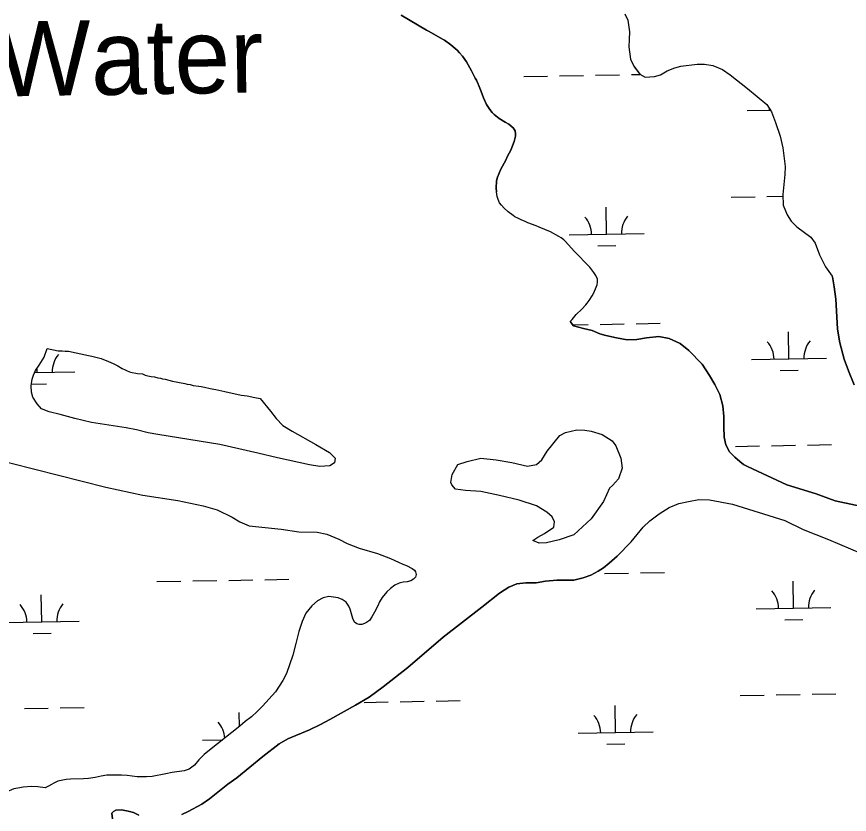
# Model space of a CAD drawing. Extents: x 3957609 to 3995875, y 234277 to 260273.
# Drawn here: x 3974548 to 3975660, y 243520 to 244584 of the extents above; entities that cross this region are included whole.
import ezdxf

# ---------------------------------------------------------------- set-up
doc = ezdxf.new("R2010")
doc.units = 0
for name, color, linetype in [('V-RIVR-IDEN', 7, 'Continuous'), ('V-TOPO-SHOR', 7, 'Continuous'), ('V-WETL-SWMP', 7, 'Continuous')]:
    doc.layers.add(name, color=color, linetype=linetype)

msp = doc.modelspace()

# ---------------------------------------------------------------- linework, layer by layer
at = {"layer": 'V-TOPO-SHOR'}
for points in [[(3975061.893, 244586.214), (3975095.656, 244566.531), (3975099.189, 244564.622), (3975116.687, 244554.464), (3975119.452, 244553.03), (3975128.031, 244546.87), (3975133.997, 244541.983), (3975136.284, 244539.784), (3975139.485, 244536.333), (3975143.44, 244531.631), (3975149.062, 244524.274), (3975155.544, 244512.263), (3975160.508, 244502.441), (3975162.171, 244499.784), (3975163.517, 244496.514), (3975166.07, 244491.216), (3975168.606, 244484.523), (3975171.578, 244475.966), (3975175.475, 244467.242), (3975177.289, 244464.274), (3975180.019, 244460.52), (3975183.366, 244456.449), (3975185.959, 244453.778), (3975192.535, 244448.267), (3975200.358, 244443.509), (3975205.275, 244440.962), (3975211.083, 244435.924), (3975213.965, 244431.858), (3975214.373, 244427.982), (3975214.327, 244424.887), (3975212.675, 244417.637), (3975208.022, 244406.25), (3975203.727, 244398.265), (3975201.327, 244392.883), (3975194.648, 244380.753), (3975190.317, 244370.136), (3975189.004, 244365.046), (3975188.707, 244355.298), (3975189.102, 244350.495)], [(3975360.305, 244588.291), (3975364.522, 244579.54), (3975366.469, 244563.991), (3975366.326, 244554.061), (3975365.562, 244544.296), (3975367.958, 244527.656), (3975372.935, 244517.649), (3975380.392, 244507.454), (3975387.629, 244503.624), (3975399.745, 244504.38), (3975407.851, 244506.901), (3975417.082, 244511.888), (3975426.92, 244516.246), (3975435.331, 244518.296), (3975456.942, 244520.93), (3975466.719, 244520.944), (3975477.864, 244519.075), (3975490.826, 244513.922), (3975500.966, 244506.791), (3975524.286, 244488.293), (3975549.743, 244467.283)], [(3975549.743, 244467.283), (3975556.276, 244457.567), (3975561.496, 244443.059), (3975567.747, 244424.656), (3975571.089, 244409.087), (3975574.458, 244384.519), (3975573.989, 244373.66), (3975571.12, 244347.01), (3975571.533, 244332.727), (3975577.241, 244319.761), (3975582.554, 244311.461), (3975589.89, 244303.75), (3975608.78, 244290.129), (3975614.558, 244281.82), (3975620.231, 244266.374), (3975628.222, 244250.272), (3975637.203, 244238.191)], [(3975287.191, 244177.265), (3975290.177, 244180.319), (3975295.531, 244186.586), (3975303.069, 244194.061), (3975308.257, 244199.558), (3975309.996, 244202.009), (3975312.83, 244205.372), (3975316.791, 244211.662), (3975319.017, 244215.809), (3975322.22, 244223.192), (3975323.193, 244226.272), (3975324.018, 244229.819), (3975323.771, 244234.003), (3975321.675, 244238.986), (3975318.947, 244242.896), (3975313.633, 244249.939), (3975292.893, 244271.289), (3975281.315, 244284.148), (3975279.026, 244286.348), (3975275.196, 244289.191), (3975272.282, 244290.936), (3975261.227, 244296.977), (3975253.69, 244300.338), (3975245.994, 244303.236), (3975241.842, 244305.153), (3975230.914, 244309.337), (3975226.298, 244311.26), (3975222.608, 244312.861), (3975217.688, 244315.256), (3975213.695, 244317.324), (3975211.085, 244318.911), (3975204.503, 244323.96), (3975199.156, 244328.68), (3975195.502, 244332.911), (3975193.225, 244335.885), (3975191.275, 244340.247), (3975190.098, 244344.446), (3975189.102, 244350.495)], [(3975666.755, 244093.119), (3975658.821, 244111.656), (3975653.007, 244127.065), (3975647.291, 244149.128), (3975644.463, 244167.433), (3975643.617, 244183.854), (3975642.097, 244207.094), (3975640.015, 244223.532), (3975637.733, 244237.032), (3975637.203, 244238.191)], [(3975287.191, 244177.265), (3975291.91, 244171.625), (3975305.015, 244168.029), (3975316.586, 244165.539), (3975327.049, 244161.207), (3975334.912, 244158.928), (3975349.414, 244155.62), (3975363.303, 244152.788), (3975376.158, 244153.373), (3975389.35, 244155.659), (3975405.936, 244157.277), (3975419.521, 244154.758), (3975434.127, 244147.889), (3975445.911, 244138.74), (3975463.604, 244120.528), (3975473.602, 244105.522), (3975480.703, 244093.5), (3975487.164, 244080.094), (3975491.125, 244065.023), (3975492.62, 244050.758), (3975492.419, 244036.986), (3975492.989, 244022.891), (3975495.01, 244012.801), (3975500.136, 244003.439), (3975507.001, 243996.374), (3975514.038, 243990.699), (3975518.929, 243986.447), (3975523.999, 243983.897), (3975576.735, 243959.295), (3975615.881, 243947.427), (3975640.975, 243937.93), (3975701.93, 243925.126)], [(3974873.241, 244074.663), (3974887.114, 244057.783), (3974894.712, 244048.075), (3974903.556, 244038.814), (3974916.139, 244031.202), (3974947.917, 244013.094), (3974966.028, 244002.46), (3974973.505, 243995.075), (3974972.643, 243988.896), (3974966.392, 243984.964), (3974952.915, 243984.075), (3974939.324, 243986.285), (3974896.582, 243995.575), (3974870.354, 244001.529), (3974819.6, 244013.409), (3974736.67, 244026.688), (3974724.012, 244029.039), (3974708.279, 244032.828), (3974694.541, 244035.505), (3974648.049, 244042.525), (3974626.15, 244048.106), (3974606.571, 244053.499), (3974591.758, 244056.655), (3974581.604, 244060.982), (3974575.814, 244067.413), (3974570.061, 244076.319), (3974568.304, 244083.156), (3974567.805, 244091.366), (3974568.863, 244100.328), (3974570.799, 244105.718), (3974573.678, 244112.178), (3974578.27, 244119.231), (3974584.928, 244129.971), (3974589.272, 244141.362)], [(3974589.272, 244141.362), (3974603.622, 244138.368), (3974608.883, 244138.292), (3974613.055, 244137.766), (3974617.542, 244137.7), (3974644.392, 244131.894), (3974648.866, 244131.054), (3974661.361, 244128.087), (3974664.437, 244126.805), (3974667.665, 244125.209), (3974677.207, 244121.357), (3974683.504, 244118.168), (3974689.181, 244114.681), (3974693.023, 244112.768), (3974695.948, 244111.641), (3974700.413, 244110.03), (3974709.672, 244108.039), (3974716.127, 244107.396)], [(3974716.127, 244107.396), (3974719.973, 244105.948), (3974723.522, 244105.123), (3974727.995, 244104.127), (3974732.32, 244103.445), (3974736.638, 244102.3), (3974740.191, 244101.784), (3974743.12, 244100.967), (3974746.824, 244100.295), (3974756.54, 244097.987), (3974772.742, 244094.502), (3974775.826, 244093.682), (3974779.842, 244093.16), (3974784.008, 244092.171), (3974791.573, 244090.977), (3974794.819, 244090.621), (3974799.141, 244089.783), (3974806.7, 244087.973), (3974814.417, 244086.465), (3974826.141, 244083.819), (3974848.209, 244079.32), (3974855.936, 244078.433), (3974866.423, 244075.959), (3974873.241, 244074.663)], [(3975339.935, 243955.119), (3975332.059, 243937.277), (3975315.396, 243914.12), (3975292.229, 243892.69), (3975272.542, 243885.901), (3975255.613, 243881.792), (3975245.811, 243881.391), (3975237.707, 243885.319), (3975244.3, 243889.577), (3975253.076, 243894.346), (3975265.714, 243902.868), (3975266.361, 243909.934), (3975263.193, 243916.51), (3975256.213, 243923.141), (3975242.186, 243931.507), (3975219.439, 243938.913), (3975192.869, 243945.282), (3975167.914, 243950.544), (3975147.798, 243951.924), (3975134.222, 243953.753), (3975129.403, 243959.266), (3975127.82, 243962.553), (3975129.61, 243973.41), (3975137.417, 243986.357), (3975149.992, 243990.529), (3975168.016, 243995.163), (3975188.66, 243992.687), (3975209.285, 243989.122), (3975230.439, 243984.463), (3975242.44, 243986.463), (3975249.608, 243992.89), (3975256.846, 244004.211), (3975273.478, 244025.193), (3975281.158, 244029.435), (3975296.444, 244033.023), (3975306.774, 244032.328), (3975315.464, 244031.114), (3975330.089, 244026.549), (3975343.573, 244018.189), (3975348.373, 244011.59), (3975355.209, 243995.165), (3975356.643, 243981.54), (3975352.086, 243967.458), (3975343.792, 243958.328), (3975339.935, 243955.119)], [(3974508.83, 243996.177), (3974667.366, 243956.417), (3974716.897, 243945.792), (3974763.53, 243938.305), (3974797.482, 243931.466), (3974815.826, 243926.246), (3974835.953, 243916.047), (3974846.392, 243910.169), (3974858.541, 243904.732), (3974901.508, 243900.392), (3974925.133, 243896.644), (3974949.429, 243896.29), (3974962.546, 243893.624), (3974978.547, 243887.045), (3974989.76, 243881.155), (3975005.454, 243874.737), (3975030.276, 243867.876), (3975047.51, 243860.97), (3975058.253, 243856.172)], [(3975350.001, 243864.308), (3975368.695, 243883.232), (3975384.77, 243902.964), (3975393.716, 243911.349), (3975406.08, 243920.61), (3975419.668, 243929.083), (3975432.286, 243934.473), (3975445.33, 243937.377), (3975459.141, 243939.81), (3975473.379, 243939.601), (3975504.251, 243933.58), (3975574.057, 243911.98), (3975598.493, 243899.862), (3975632.351, 243886.367), (3975676.508, 243867.925)], [(3975350.001, 243864.308), (3975339.581, 243854.847), (3975332.067, 243848.791), (3975324.547, 243843.97), (3975315.021, 243838.981), (3975304.72, 243835.221), (3975292.412, 243832.218), (3975269.456, 243831.925), (3975254.515, 243830.756), (3975241.894, 243828.677), (3975228.332, 243828.749), (3975216.015, 243827.289), (3975205.255, 243822.908), (3975193.129, 243814.976), (3975169.36, 243796.19), (3975117.981, 243756.125), (3975070.613, 243715.468), (3975037.64, 243689.536), (3975018.768, 243676.171), (3975000.653, 243665.12), (3974966.407, 243645.961), (3974953.965, 243639.26), (3974939.523, 243632.547), (3974910.318, 243620.506), (3974898.802, 243613.811), (3974876.872, 243596.575), (3974842.218, 243568.168), (3974830.405, 243559.621), (3974805.715, 243540.364), (3974795.587, 243533.216), (3974777.157, 243523.243), (3974769.012, 243519.497)], [(3975058.253, 243856.172), (3975063.967, 243853.587), (3975068.754, 243851.769), (3975076.556, 243847.812), (3975079.422, 243845.362), (3975080.898, 243843.062), (3975081.613, 243839.524), (3975080.71, 243836.13), (3975078.26, 243833.496), (3975074.732, 243831.088), (3975069.657, 243829.978), (3975064.5, 243829.255), (3975059.038, 243828.143), (3975053.432, 243825.491), (3975047.528, 243821.065), (3975042.625, 243816.568), (3975036.356, 243808.982), (3975032.619, 243803.028), (3975030.339, 243797.855), (3975026.077, 243789.28), (3975022.493, 243783.251), (3975019.212, 243778.378), (3975015.608, 243775.816), (3975012.614, 243774.102), (3975009.231, 243773.158), (3975005.767, 243772.906), (3975002.525, 243773.965), (3974999.584, 243776.181), (3974997.399, 243781.096), (3974993.705, 243793.552), (3974991.909, 243797.624), (3974988.488, 243802.608), (3974982.998, 243806.426), (3974977.671, 243808.627), (3974971.273, 243809.668), (3974965.26, 243810.401), (3974957.414, 243808.582), (3974949.968, 243804.609), (3974942.23, 243797.861), (3974934.511, 243787.957), (3974929.338, 243777.144), (3974925.107, 243763.795), (3974920.968, 243747.749), (3974917.288, 243732.169), (3974908.809, 243707.702), (3974903.705, 243698.199), (3974893.863, 243683.122), (3974876.647, 243664.069), (3974869.526, 243657.018), (3974861.715, 243649.809), (3974853.357, 243643.52), (3974846.388, 243637.316), (3974805.991, 243605.341), (3974798.788, 243599.213), (3974791.743, 243592.316), (3974785.933, 243585.348), (3974778.726, 243579.759), (3974772.039, 243577.642), (3974755.956, 243575.309), (3974747.572, 243573.796), (3974729.341, 243569.913), (3974721.564, 243569.556), (3974714.556, 243569.515), (3974709.086, 243569.714), (3974696.059, 243571.483), (3974688.432, 243571.977), (3974668.562, 243571.702), (3974661.253, 243570.502), (3974653.329, 243568.913), (3974644.406, 243567.398), (3974637.475, 243566.894), (3974620.227, 243566.326), (3974614.223, 243565.905), (3974603.298, 243563.683), (3974597.922, 243561.34), (3974594.621, 243559.472), (3974590.941, 243556.986), (3974586.239, 243554.745)], [(3974586.239, 243554.745), (3974576.648, 243556.388), (3974568.302, 243556.646), (3974556.872, 243555.65), (3974552.395, 243555.005), (3974544.679, 243553.414), (3974541.285, 243552.466), (3974537.279, 243550.588), (3974529.724, 243547.606), (3974522.175, 243544.005), (3974518.171, 243541.509), (3974515.556, 243539.485), (3974500.925, 243531.361), (3974496.612, 243529.172)], [(3974711.546, 243518.223), (3974704.437, 243521.881), (3974697.336, 243523.841), (3974688.082, 243525.326), (3974680.842, 243524.973), (3974677.461, 243523.413), (3974675.318, 243520.933), (3974676.289, 243513.39)]]:
    msp.add_lwpolyline(points, dxfattribs=at)
at = {"layer": 'V-WETL-SWMP'}
for p, q in [((3975369.267, 244507.158), (3975380.564, 244507.363)), ((3975225.291, 244504.54), (3975257.285, 244505.122)), ((3975273.283, 244505.413), (3975305.277, 244505.994)), ((3975321.275, 244506.285), (3975353.269, 244506.867)), ((3975523.48, 244459.212), (3975554.787, 244459.781)), ((3975502.174, 244343.373), (3975534.169, 244343.955)), ((3975550.166, 244344.246), (3975571.188, 244344.628)), ((3975335.982, 244293.914), (3975335.328, 244329.908)), ((3975285.99, 244293.005), (3975385.974, 244294.823)), ((3975324.265, 244278.267), (3975348.261, 244278.703)), ((3975327.323, 244173.665), (3975359.317, 244174.247)), ((3975375.315, 244174.538), (3975407.31, 244175.12)), ((3975290.759, 244173), (3975311.325, 244173.374)), ((3975579.52, 244127.501), (3975578.865, 244163.495)), ((3975529.528, 244126.592), (3975629.511, 244128.41)), ((3974572.345, 244109.187), (3974625.861, 244110.16)), ((3974575.87, 244109.251), (3974575.758, 244115.373)), ((3975567.802, 244111.854), (3975591.798, 244112.29)), ((3974568.077, 244093.676), (3974588.148, 244094.041)), ((3975508.222, 244010.753), (3975540.217, 244011.335)), ((3975556.215, 244011.626), (3975588.209, 244012.208)), ((3975604.207, 244012.498), (3975636.201, 244013.08)), ((3975333.371, 243841.045), (3975365.366, 243841.627)), ((3975381.363, 243841.918), (3975413.358, 243842.5)), ((3974735.562, 243830.175), (3974767.556, 243830.757)), ((3974783.554, 243831.048), (3974815.548, 243831.63)), ((3974831.546, 243831.921), (3974863.541, 243832.502)), ((3974879.538, 243832.793), (3974911.533, 243833.375)), ((3975585.568, 243794.881), (3975584.913, 243830.875)), ((3974581.918, 243776.631), (3974581.263, 243812.625)), ((3975535.576, 243793.972), (3975635.56, 243795.79)), ((3974531.926, 243775.722), (3974631.909, 243777.54)), ((3975573.85, 243779.234), (3975597.846, 243779.67)), ((3974570.2, 243760.985), (3974594.196, 243761.421)), ((3975514.27, 243678.133), (3975546.265, 243678.715)), ((3975562.263, 243679.006), (3975594.257, 243679.588)), ((3975610.255, 243679.878), (3975642.249, 243680.46)), ((3975012.445, 243669.008), (3975044.44, 243669.59)), ((3975060.438, 243669.881), (3975092.432, 243670.463)), ((3975108.43, 243670.754), (3975140.424, 243671.335)), ((3975348.078, 243628.674), (3975347.424, 243664.668)), ((3974558.612, 243660.756), (3974590.607, 243661.338)), ((3974606.605, 243661.629), (3974638.599, 243662.211)), ((3974845.937, 243636.959), (3974845.599, 243655.543)), ((3975298.086, 243627.765), (3975398.07, 243629.583)), ((3974796.261, 243618.64), (3974823.416, 243619.134)), ((3975336.361, 243613.027), (3975360.357, 243613.463))]:
    msp.add_line(p, q, dxfattribs=at)
for points in [[(3975492.989, 244022.891), (3975492.42, 244036.986), (3975492.62, 244050.759), (3975491.124, 244065.022), (3975487.164, 244080.094), (3975480.703, 244093.5), (3975473.602, 244105.522), (3975463.604, 244120.527), (3975445.912, 244138.74), (3975434.126, 244147.889), (3975419.521, 244154.757), (3975405.936, 244157.276), (3975389.35, 244155.659), (3975376.159, 244153.374), (3975363.303, 244152.787), (3975349.413, 244155.62), (3975334.911, 244158.927), (3975327.05, 244161.208), (3975316.587, 244165.539), (3975305.014, 244168.029), (3975291.909, 244171.625), (3975287.192, 244177.266), (3975290.178, 244180.318), (3975295.531, 244186.586), (3975303.069, 244194.061), (3975308.257, 244199.558), (3975309.995, 244202.009), (3975312.83, 244205.373), (3975316.791, 244211.661), (3975319.018, 244215.808), (3975322.22, 244223.191), (3975323.194, 244226.272), (3975324.019, 244229.82), (3975323.771, 244234.003), (3975321.676, 244238.986), (3975318.947, 244242.895), (3975313.632, 244249.938), (3975292.892, 244271.289), (3975281.315, 244284.149), (3975279.026, 244286.349), (3975275.197, 244289.191), (3975272.282, 244290.935), (3975261.226, 244296.978), (3975253.69, 244300.337), (3975245.993, 244303.235), (3975241.842, 244305.153), (3975230.914, 244309.336), (3975226.298, 244311.26), (3975222.607, 244312.862), (3975217.689, 244315.255), (3975213.694, 244317.325), (3975211.086, 244318.911), (3975204.504, 244323.959), (3975199.155, 244328.68), (3975195.502, 244332.912), (3975193.224, 244335.886), (3975191.275, 244340.248), (3975190.097, 244344.445), (3975189.102, 244350.495), (3975188.707, 244355.299), (3975189.004, 244365.046), (3975190.316, 244370.135), (3975194.649, 244380.752), (3975201.326, 244392.882), (3975203.726, 244398.265), (3975208.021, 244406.251), (3975212.675, 244417.637), (3975214.328, 244424.887), (3975214.373, 244427.982), (3975213.965, 244431.858), (3975211.083, 244435.924), (3975205.275, 244440.961), (3975200.359, 244443.509), (3975192.534, 244448.266), (3975185.959, 244453.779), (3975183.366, 244456.448), (3975180.02, 244460.521), (3975177.289, 244464.275), (3975175.474, 244467.242), (3975171.577, 244475.966), (3975168.605, 244484.522), (3975166.071, 244491.215), (3975163.517, 244496.514), (3975162.172, 244499.784), (3975160.508, 244502.44), (3975155.543, 244512.263), (3975149.061, 244524.275), (3975143.441, 244531.631), (3975139.485, 244536.332), (3975136.285, 244539.784), (3975133.996, 244541.984), (3975128.03, 244546.869), (3975119.452, 244553.03), (3975116.687, 244554.463), (3975099.189, 244564.623), (3975095.657, 244566.531), (3975061.892, 244586.214)], [(3975360.304, 244588.291), (3975364.522, 244579.539), (3975366.469, 244563.991), (3975366.325, 244554.061), (3975365.562, 244544.295), (3975367.959, 244527.655), (3975372.935, 244517.65), (3975380.391, 244507.455), (3975387.629, 244503.625), (3975399.745, 244504.38), (3975407.852, 244506.901), (3975417.081, 244511.888), (3975426.921, 244516.246), (3975435.331, 244518.296), (3975456.941, 244520.931), (3975466.718, 244520.944), (3975477.865, 244519.075), (3975490.826, 244513.921), (3975500.965, 244506.79), (3975524.286, 244488.294), (3975549.743, 244467.283), (3975556.275, 244457.567), (3975561.496, 244443.058), (3975567.747, 244424.655), (3975571.09, 244409.087), (3975574.458, 244384.518), (3975573.99, 244373.661), (3975571.119, 244347.01), (3975571.533, 244332.726), (3975577.242, 244319.762), (3975582.553, 244311.46), (3975589.89, 244303.749), (3975608.781, 244290.128), (3975614.557, 244281.819), (3975620.23, 244266.373), (3975628.222, 244250.272), (3975637.203, 244238.192), (3975637.733, 244237.032), (3975640.014, 244223.532), (3975642.097, 244207.094), (3975643.617, 244183.854), (3975644.462, 244167.433), (3975647.292, 244149.127), (3975653.008, 244127.064), (3975658.821, 244111.655), (3975666.756, 244093.12)], [(3975339.935, 243955.119), (3975332.059, 243937.277), (3975315.396, 243914.12), (3975292.229, 243892.69), (3975272.542, 243885.901), (3975255.613, 243881.792), (3975245.811, 243881.391), (3975237.707, 243885.319), (3975244.3, 243889.577), (3975253.076, 243894.346), (3975265.714, 243902.868), (3975266.361, 243909.934), (3975263.193, 243916.51), (3975256.213, 243923.141), (3975242.186, 243931.507), (3975219.439, 243938.913), (3975192.869, 243945.282), (3975167.914, 243950.544), (3975147.798, 243951.924), (3975134.222, 243953.753), (3975129.403, 243959.266), (3975127.82, 243962.553), (3975129.61, 243973.41), (3975137.417, 243986.357), (3975149.992, 243990.529), (3975168.016, 243995.163), (3975188.66, 243992.687), (3975209.285, 243989.122), (3975230.439, 243984.463), (3975242.44, 243986.463), (3975249.608, 243992.89), (3975256.846, 244004.211), (3975273.478, 244025.193), (3975281.158, 244029.435), (3975296.444, 244033.023), (3975306.774, 244032.328), (3975315.464, 244031.114), (3975330.089, 244026.549), (3975343.573, 244018.189), (3975348.373, 244011.59), (3975355.209, 243995.165), (3975356.643, 243981.54), (3975352.086, 243967.458), (3975343.792, 243958.328), (3975339.935, 243955.119)], [(3975701.93, 243925.125), (3975640.974, 243937.929), (3975615.881, 243947.426), (3975576.736, 243959.294), (3975524, 243983.898), (3975518.929, 243986.448), (3975514.037, 243990.699), (3975507, 243996.373), (3975500.137, 244003.439), (3975495.01, 244012.801), (3975492.989, 244022.891)], [(3974508.83, 243996.177), (3974667.366, 243956.418), (3974716.896, 243945.793), (3974763.53, 243938.305), (3974797.482, 243931.466), (3974815.825, 243926.247), (3974835.953, 243916.048), (3974846.393, 243910.17), (3974858.541, 243904.731), (3974901.507, 243900.392), (3974925.134, 243896.644), (3974949.429, 243896.291), (3974962.546, 243893.624), (3974978.548, 243887.046), (3974989.761, 243881.156), (3975005.455, 243874.737), (3975030.275, 243867.876), (3975047.51, 243860.97), (3975058.253, 243856.172), (3975063.968, 243853.588), (3975068.754, 243851.769), (3975076.557, 243847.811), (3975079.421, 243845.363), (3975080.898, 243843.062), (3975081.613, 243839.523), (3975080.709, 243836.129), (3975078.26, 243833.496), (3975074.732, 243831.087), (3975069.656, 243829.978), (3975064.5, 243829.254), (3975059.038, 243828.142), (3975053.432, 243825.49), (3975047.528, 243821.064), (3975042.626, 243816.567), (3975036.356, 243808.982), (3975032.618, 243803.029), (3975030.339, 243797.855), (3975026.078, 243789.28), (3975022.494, 243783.251), (3975019.212, 243778.379), (3975015.607, 243775.816), (3975012.614, 243774.103), (3975009.231, 243773.159), (3975005.767, 243772.907), (3975002.525, 243773.965), (3974999.585, 243776.181), (3974997.399, 243781.097), (3974993.704, 243793.552), (3974991.908, 243797.623), (3974988.489, 243802.608), (3974982.998, 243806.426), (3974977.67, 243808.628), (3974971.272, 243809.667), (3974965.26, 243810.401), (3974957.415, 243808.582), (3974949.968, 243804.609), (3974942.23, 243797.862), (3974934.511, 243787.957), (3974929.339, 243777.143), (3974925.106, 243763.794), (3974920.967, 243747.749), (3974917.287, 243732.169), (3974908.809, 243707.703), (3974903.706, 243698.199), (3974893.862, 243683.121), (3974876.648, 243664.07), (3974869.527, 243657.019), (3974861.715, 243649.809), (3974853.358, 243643.52), (3974846.387, 243637.316), (3974805.991, 243605.341), (3974798.788, 243599.213), (3974791.744, 243592.316), (3974785.933, 243585.349)], [(3974769.013, 243519.496), (3974777.157, 243523.243), (3974795.588, 243533.216), (3974805.714, 243540.365), (3974830.406, 243559.621), (3974842.219, 243568.167), (3974876.872, 243596.575), (3974898.802, 243613.811), (3974910.319, 243620.506), (3974939.523, 243632.547), (3974953.966, 243639.26), (3974966.407, 243645.961), (3975000.653, 243665.12), (3975018.769, 243676.17), (3975037.641, 243689.536), (3975070.614, 243715.467), (3975117.981, 243756.124), (3975169.359, 243796.189), (3975193.129, 243814.977), (3975205.254, 243822.909), (3975216.014, 243827.288), (3975228.332, 243828.75), (3975241.893, 243828.677), (3975254.515, 243830.757), (3975269.455, 243831.926), (3975292.412, 243832.218), (3975304.721, 243835.22), (3975315.022, 243838.98), (3975324.546, 243843.969), (3975332.067, 243848.791), (3975339.581, 243854.846), (3975350.001, 243864.308), (3975368.696, 243883.231), (3975384.771, 243902.965), (3975393.716, 243911.349), (3975406.079, 243920.611), (3975419.669, 243929.082), (3975432.285, 243934.472), (3975445.33, 243937.378), (3975459.142, 243939.809), (3975473.379, 243939.602), (3975504.25, 243933.581), (3975574.057, 243911.98), (3975598.493, 243899.861), (3975632.351, 243886.367), (3975676.508, 243867.925)], [(3974785.933, 243585.349), (3974778.727, 243579.76), (3974772.039, 243577.641), (3974755.956, 243575.31), (3974747.571, 243573.796), (3974729.341, 243569.912), (3974721.564, 243569.557), (3974714.556, 243569.515), (3974709.086, 243569.713), (3974696.059, 243571.483), (3974688.431, 243571.976), (3974668.562, 243571.702), (3974661.253, 243570.502), (3974653.33, 243568.914), (3974644.405, 243567.397), (3974637.476, 243566.893), (3974620.227, 243566.327), (3974614.222, 243565.905), (3974603.299, 243563.683), (3974597.922, 243561.34), (3974594.622, 243559.472), (3974590.94, 243556.985), (3974586.238, 243554.746), (3974576.648, 243556.388), (3974568.302, 243556.646), (3974556.873, 243555.65), (3974552.395, 243555.005), (3974544.679, 243553.413)], [(3974676.289, 243513.389), (3974675.319, 243520.933), (3974677.461, 243523.412), (3974680.842, 243524.973), (3974688.082, 243525.325), (3974697.336, 243523.84), (3974704.436, 243521.88), (3974711.546, 243518.224)]]:
    msp.add_lwpolyline(points, dxfattribs=at)
msp.add_lwpolyline([(3974716.126, 244107.396), (3974719.974, 244105.947), (3974723.522, 244105.122), (3974727.996, 244104.128), (3974732.32, 244103.446), (3974736.637, 244102.3), (3974740.19, 244101.784), (3974743.119, 244100.968), (3974746.824, 244100.295), (3974756.541, 244097.987), (3974772.742, 244094.501), (3974775.826, 244093.682), (3974779.843, 244093.16), (3974784.007, 244092.171), (3974791.574, 244090.977), (3974794.819, 244090.621), (3974799.141, 244089.784), (3974806.699, 244087.972), (3974814.416, 244086.466), (3974826.141, 244083.82), (3974848.209, 244079.32), (3974855.935, 244078.434), (3974866.424, 244075.96), (3974873.242, 244074.663), (3974887.114, 244057.783), (3974894.713, 244048.076), (3974903.556, 244038.815), (3974916.139, 244031.202), (3974947.917, 244013.094), (3974966.028, 244002.46), (3974973.506, 243995.076), (3974972.642, 243988.897), (3974966.393, 243984.964), (3974952.914, 243984.076), (3974939.324, 243986.285), (3974896.582, 243995.575), (3974870.354, 244001.528), (3974819.6, 244013.41), (3974736.67, 244026.688), (3974724.012, 244029.039), (3974708.278, 244032.828), (3974694.54, 244035.504), (3974648.05, 244042.526), (3974626.151, 244048.107), (3974606.571, 244053.499), (3974591.757, 244056.655), (3974581.603, 244060.982), (3974575.815, 244067.413), (3974570.062, 244076.319), (3974568.304, 244083.156), (3974567.804, 244091.367), (3974568.863, 244100.329), (3974570.799, 244105.719), (3974573.679, 244112.178), (3974578.27, 244119.232), (3974584.927, 244129.971), (3974589.272, 244141.362), (3974603.623, 244138.367), (3974608.884, 244138.291), (3974613.056, 244137.766), (3974617.543, 244137.701), (3974644.391, 244131.893), (3974648.867, 244131.054), (3974661.361, 244128.087), (3974664.438, 244126.804), (3974667.665, 244125.209), (3974677.206, 244121.356), (3974683.505, 244118.169), (3974689.181, 244114.681), (3974693.023, 244112.768), (3974695.948, 244111.642), (3974700.413, 244110.03), (3974709.671, 244108.038)], close=True, dxfattribs=at)
for centre, start, end in [((3975518.229, 244459.591), 0.269879, 3.654543), ((3975280.74, 244293.384), 0.269879, 41.813537), ((3975391.207, 244295.393), 140.269876, 181.813534), ((3975524.277, 244126.971), 0.269879, 41.813537), ((3975634.745, 244128.98), 140.269876, 181.813534), ((3974631.095, 244110.73), 140.269876, 181.813534), ((3975640.793, 243796.36), 140.269876, 181.813534), ((3975530.325, 243794.351), 0.269879, 41.813537), ((3974526.675, 243776.102), 0.269879, 41.813537), ((3974637.143, 243778.11), 140.269876, 181.813534), ((3975292.836, 243628.144), 0.269879, 41.813537), ((3975403.303, 243630.153), 140.269876, 181.813534), ((3974791.011, 243619.019), 3.747133, 41.813537)]:
    msp.add_arc(centre, 35.246, start, end, dxfattribs=at)

# ---------------------------------------------------------------- texts
at = {"layer": 'V-RIVR-IDEN'}
msp.add_text('Water', height=99.9998, rotation=0.902342, dxfattribs=at).set_placement((3974521.892, 244477.73))

doc.saveas('drawing.dxf')
